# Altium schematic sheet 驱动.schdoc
size 594 x 419 mm; Symbol: Drawing-Symbol_A4; Company: 嘉立创EDA; Version: V1.0; Page Size: A4; @Project Name: FOC; @Update Date: 2026-07-20; @Create Date: 2026-07-20; Device: Drawing-Symbol_A4; @Board Name: Board1; @Page Name: P1; @Create Time: 00:30:19; @Page Count: 2; @Page No: 2; @Schematic Name: Schematic1; @Update Time: 00:30:19; @Assembly Variant: Basic; Border: 1; Title Block Position: 3; Size: A4; Width: 2338; Height: 1652; Region Start: 1; X Region Count: 6; Y Region Count: 4; Blade Width: 10
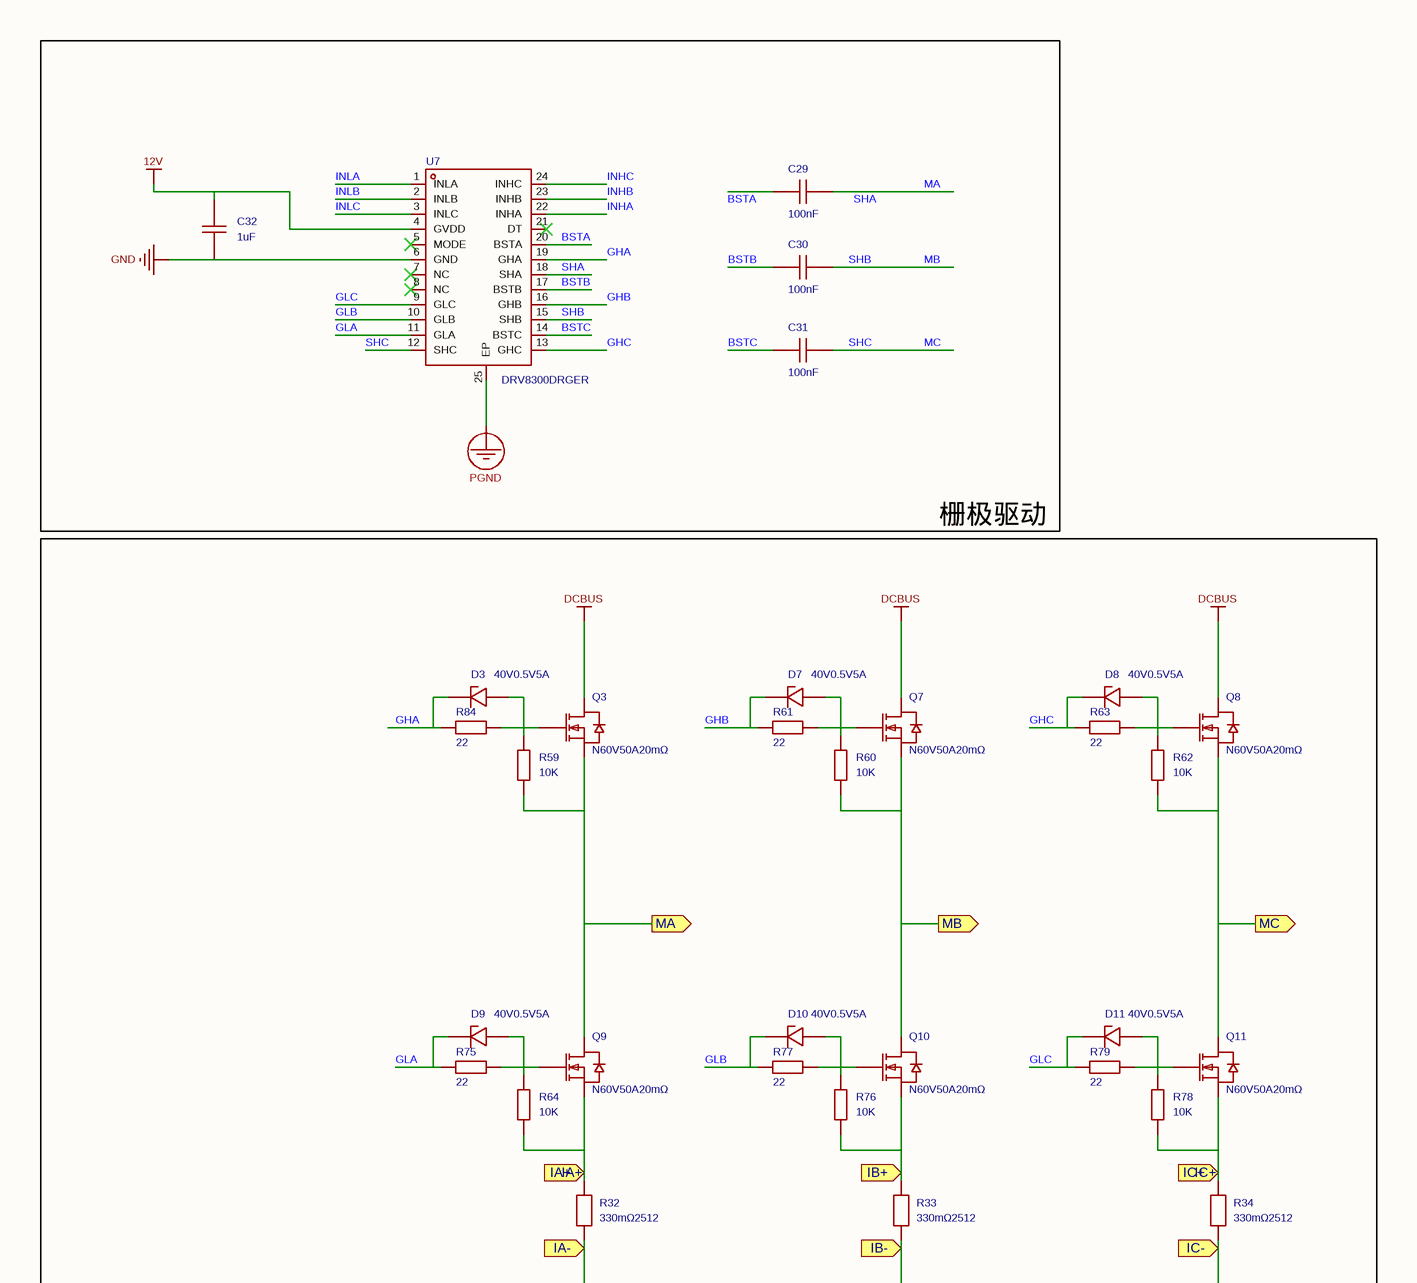
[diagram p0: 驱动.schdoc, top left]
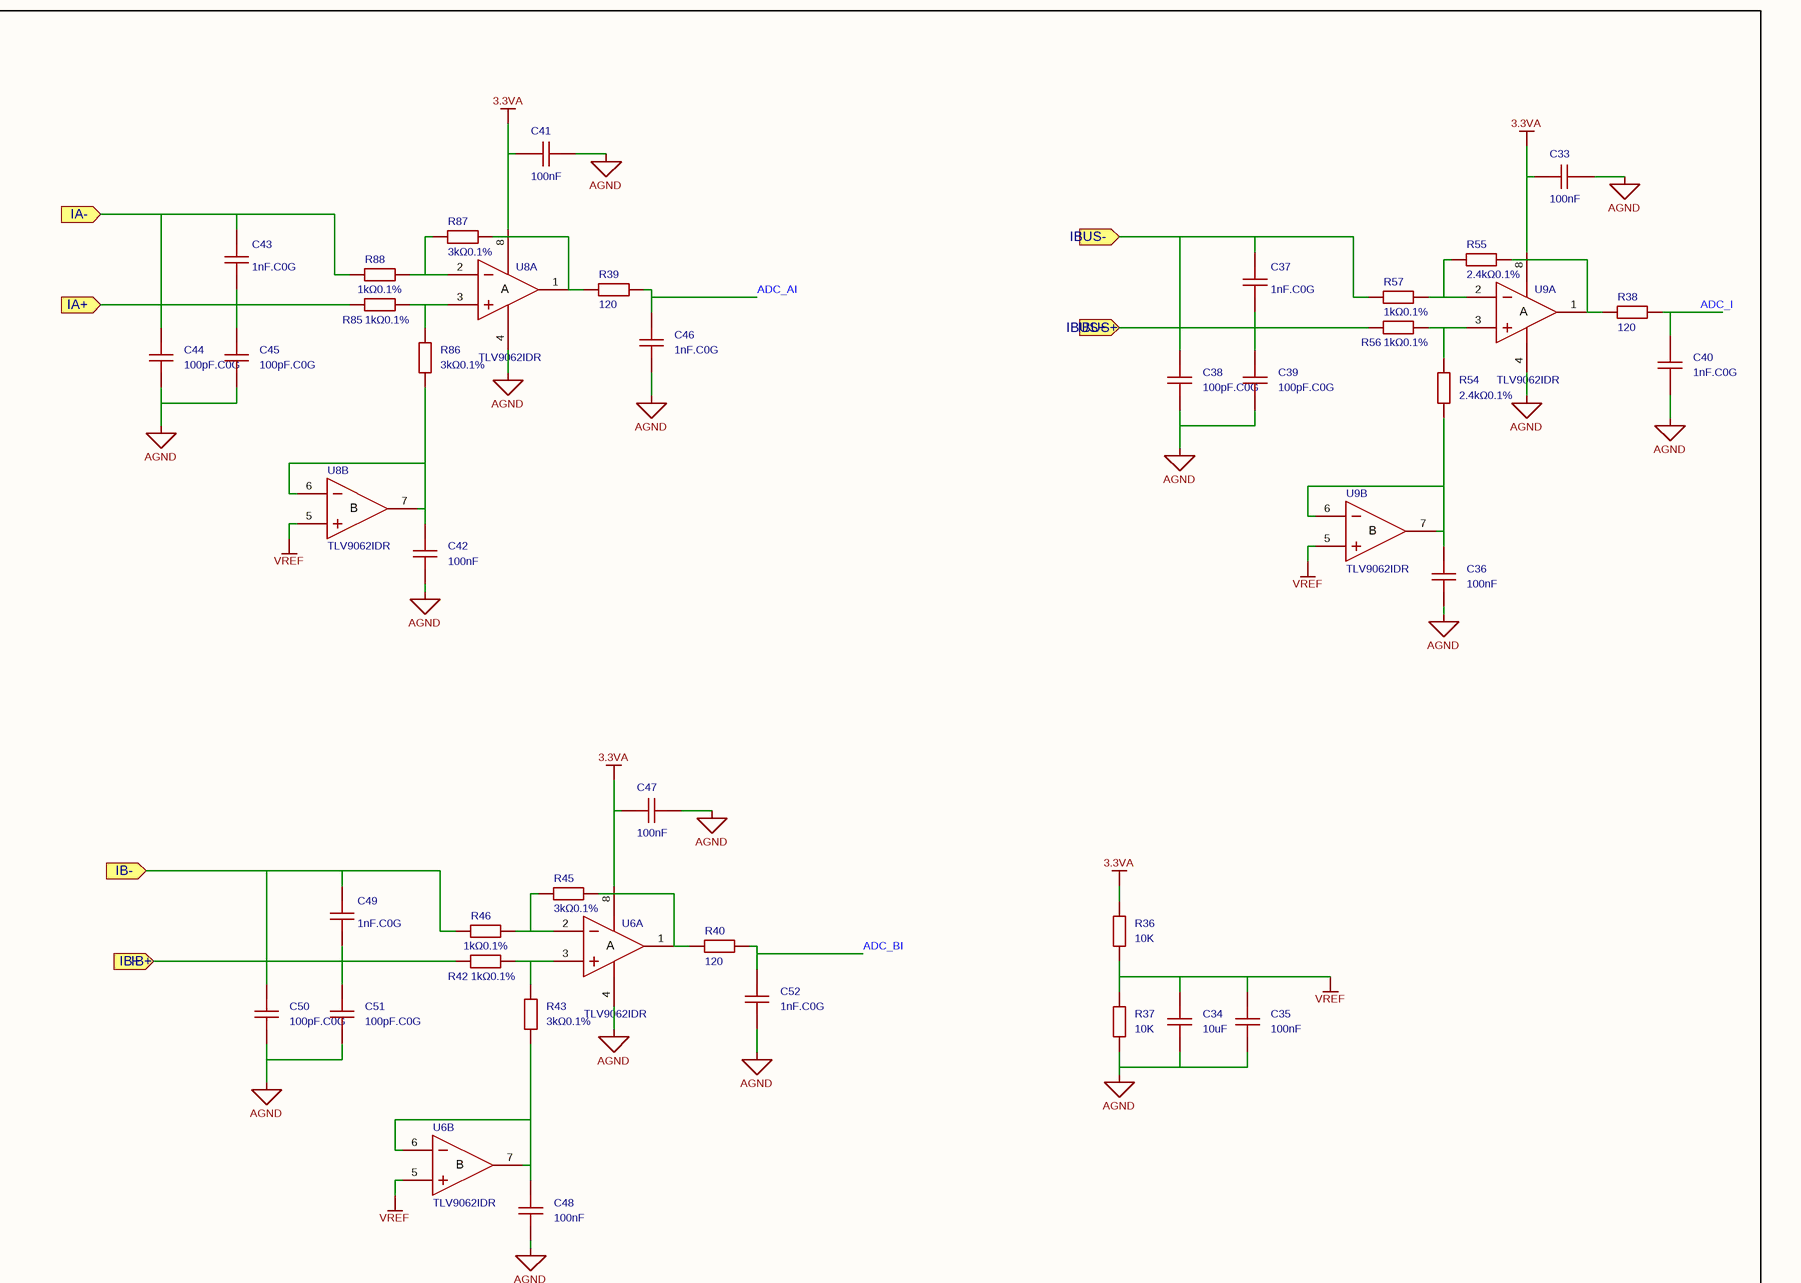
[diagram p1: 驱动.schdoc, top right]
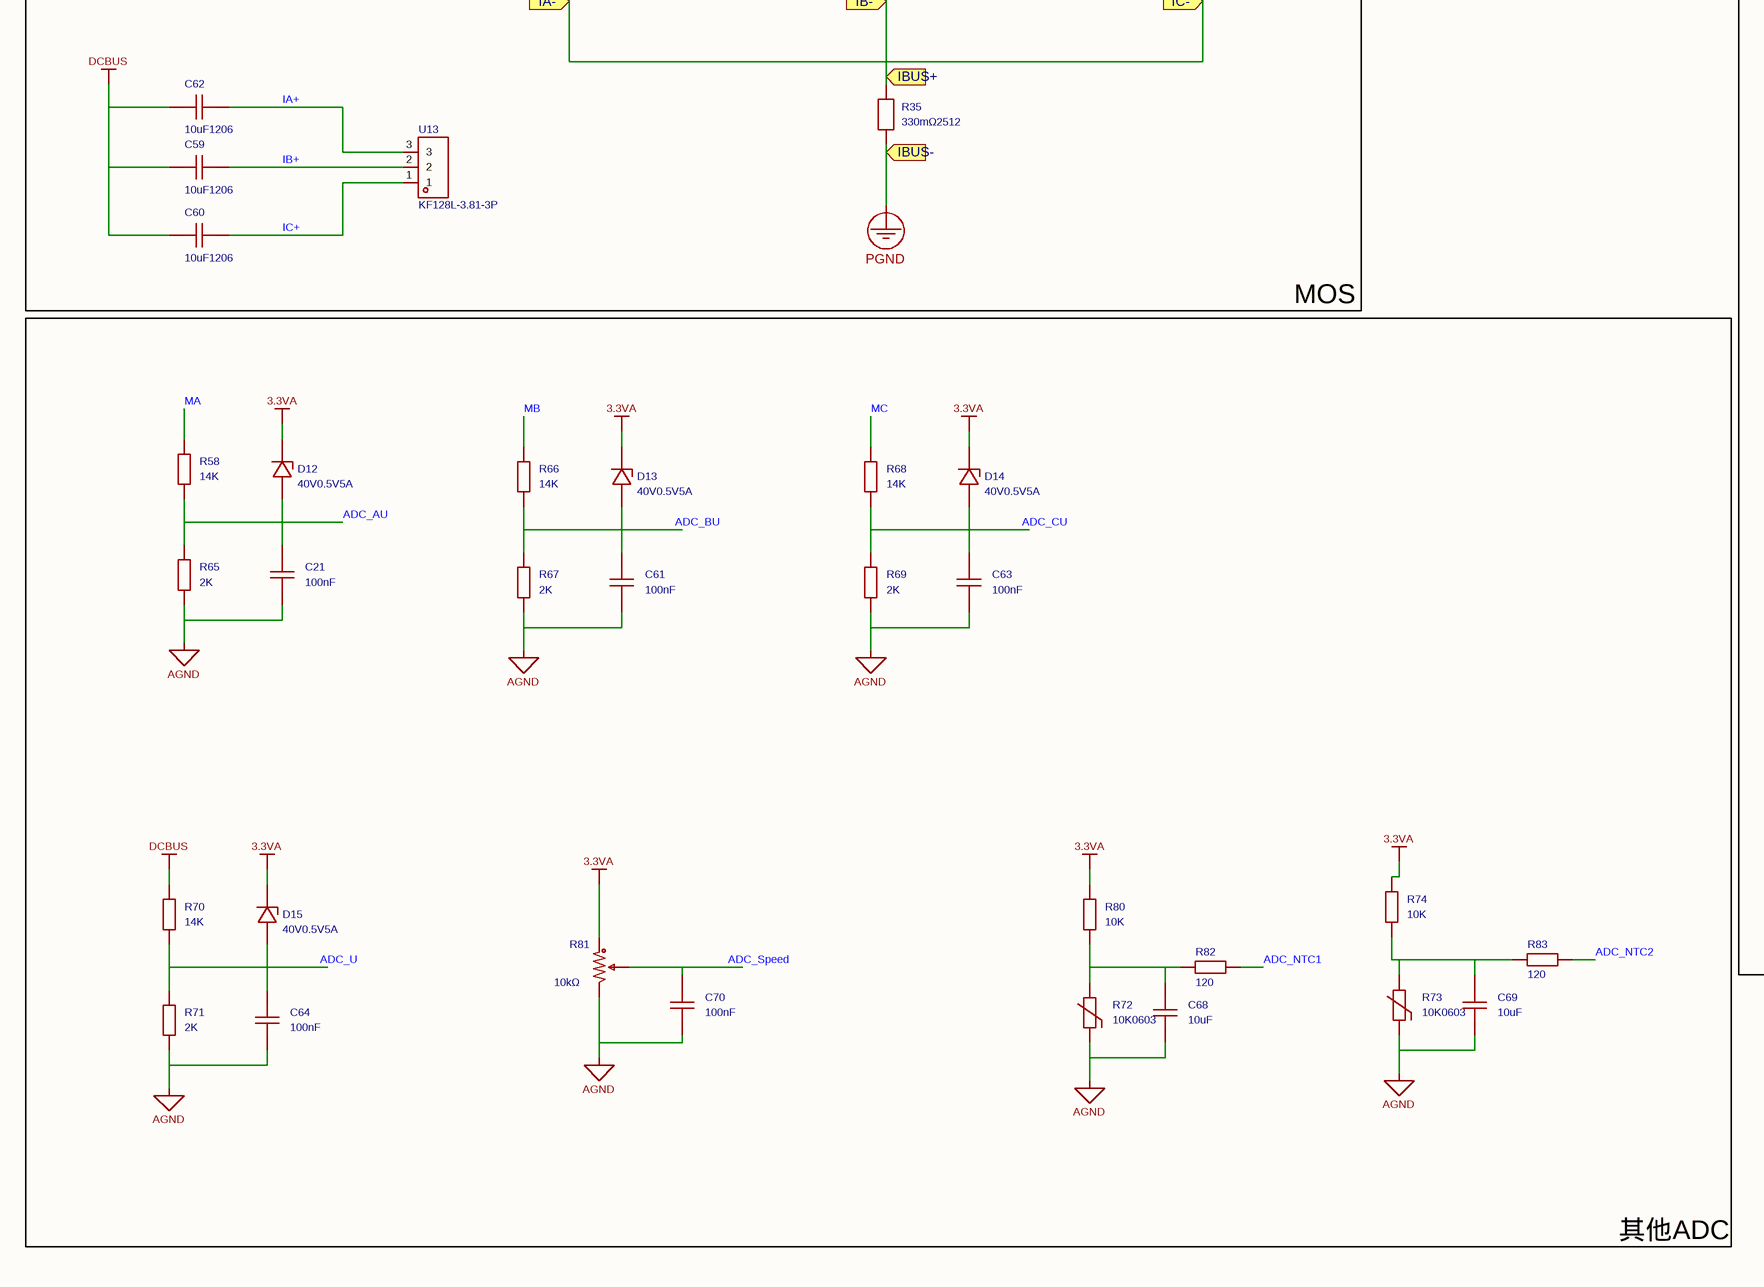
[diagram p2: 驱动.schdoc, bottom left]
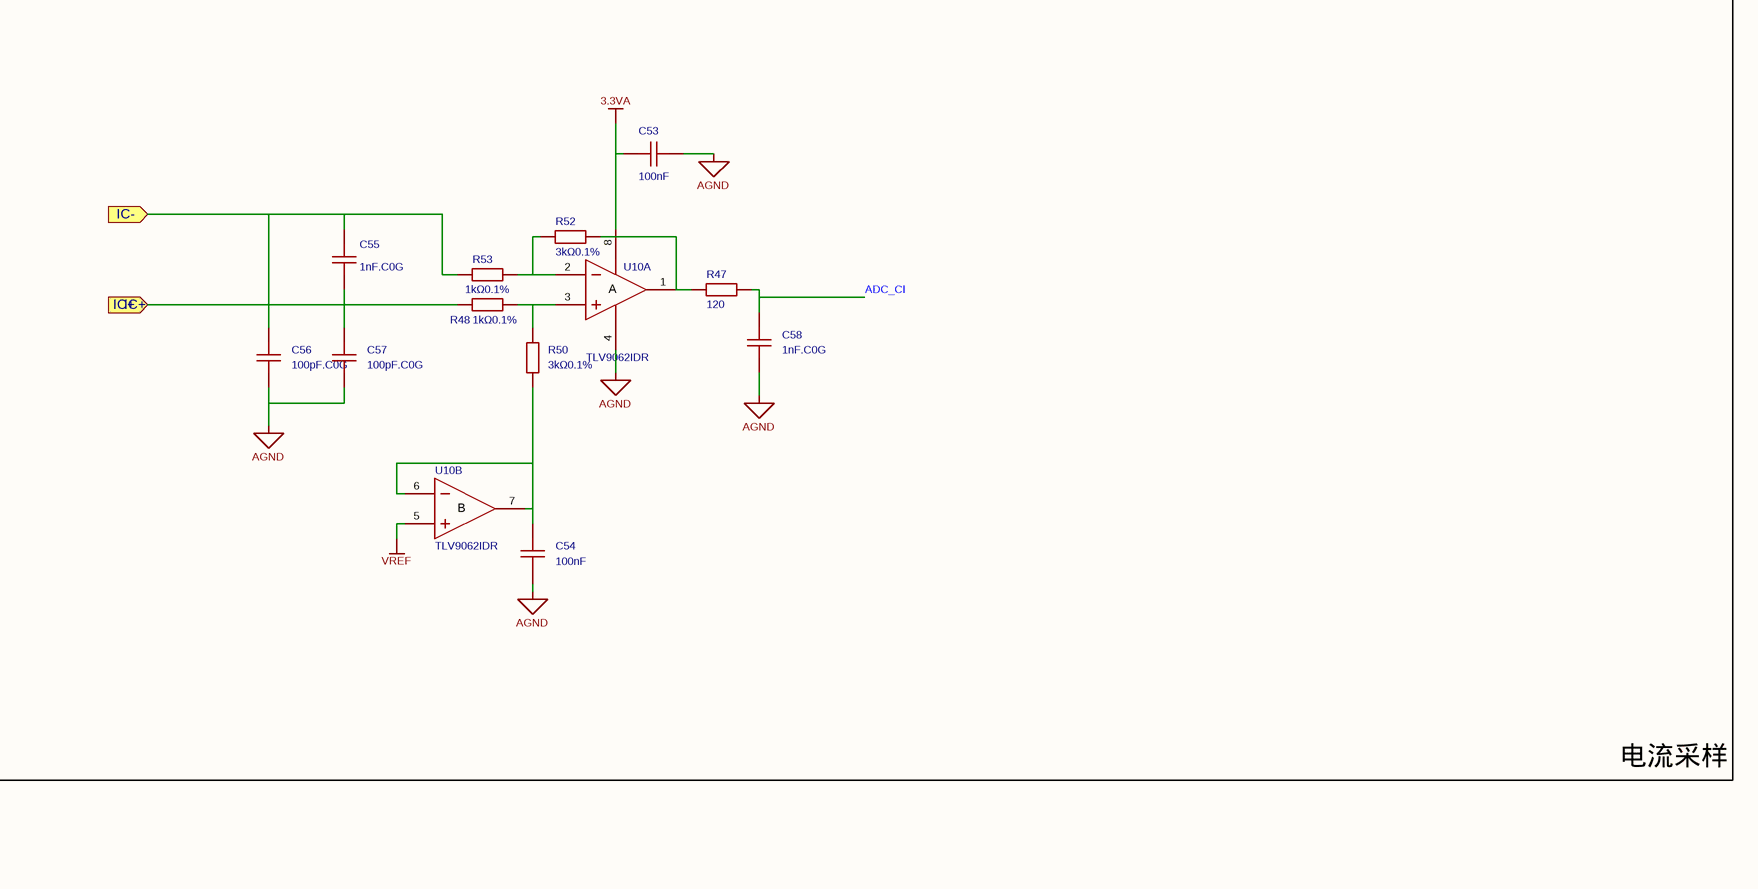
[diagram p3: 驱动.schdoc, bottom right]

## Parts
C21  100nF  [C0603]
C29  100nF  [C0603]
C30  100nF  [C0603]
C31  100nF  [C0603]
C32  1uF  [C0603]
C33  100nF  [C0603]
C34  10uF  [C0603]
C35  100nF  [C0603]
C36  100nF  [C0603]
C37  1nF.C0G  [C0603]
C38  100pF.C0G  [C0603]
C39  100pF.C0G  [C0603]
C40  1nF.C0G  [C0603]
C41  100nF  [C0603]
C42  100nF  [C0603]
C43  1nF.C0G  [C0603]
C44  100pF.C0G  [C0603]
C45  100pF.C0G  [C0603]
C46  1nF.C0G  [C0603]
C47  100nF  [C0603]
C48  100nF  [C0603]
C49  1nF.C0G  [C0603]
C50  100pF.C0G  [C0603]
C51  100pF.C0G  [C0603]
C52  1nF.C0G  [C0603]
C53  100nF  [C0603]
C54  100nF  [C0603]
C55  1nF.C0G  [C0603]
C56  100pF.C0G  [C0603]
C57  100pF.C0G  [C0603]
C58  1nF.C0G  [C0603]
C59  10uF1206  [C1206]
C60  10uF1206  [C1206]
C61  100nF  [C0603]
C62  10uF1206  [C1206]
C63  100nF  [C0603]
C64  100nF  [C0603]
C68  10uF  [C0603]
C69  10uF  [C0603]
C70  100nF  [C0603]
D3  40V0.5V5A  [SMA_L4.3-W2.6-LS5.0-FD]
D7  40V0.5V5A  [SMA_L4.3-W2.6-LS5.0-FD]
D8  40V0.5V5A  [SMA_L4.3-W2.6-LS5.0-FD]
D9  40V0.5V5A  [SMA_L4.3-W2.6-LS5.0-FD]
D10  40V0.5V5A  [SMA_L4.3-W2.6-LS5.0-FD]
D11  40V0.5V5A  [SMA_L4.3-W2.6-LS5.0-FD]
D12  40V0.5V5A  [SMA_L4.3-W2.6-LS5.0-FD]
D13  40V0.5V5A  [SMA_L4.3-W2.6-LS5.0-FD]
D14  40V0.5V5A  [SMA_L4.3-W2.6-LS5.0-FD]
D15  40V0.5V5A  [SMA_L4.3-W2.6-LS5.0-FD]
Q3  N60V50A20mΩ  [TO-252-2_L6.6-W6.1-P4.57-LS10.1-TL-CW]
Q7  N60V50A20mΩ  [TO-252-2_L6.6-W6.1-P4.57-LS10.1-TL-CW]
Q8  N60V50A20mΩ  [TO-252-2_L6.6-W6.1-P4.57-LS10.1-TL-CW]
Q9  N60V50A20mΩ  [TO-252-2_L6.6-W6.1-P4.57-LS10.1-TL-CW]
Q10  N60V50A20mΩ  [TO-252-2_L6.6-W6.1-P4.57-LS10.1-TL-CW]
Q11  N60V50A20mΩ  [TO-252-2_L6.6-W6.1-P4.57-LS10.1-TL-CW]
R32  330mΩ2512  [RES-SMD_L6.4-W3.2-JER2512XXXXXX]
R33  330mΩ2512  [RES-SMD_L6.4-W3.2-JER2512XXXXXX]
R34  330mΩ2512  [RES-SMD_L6.4-W3.2-JER2512XXXXXX]
R35  330mΩ2512  [RES-SMD_L6.4-W3.2-JER2512XXXXXX]
R36  10K  [R0603]
R37  10K  [R0603]
R38  120  [R0603]
R39  120  [R0603]
R40  120  [R0603]
R42  1kΩ0.1%  [R0603]
R43  3kΩ0.1%  [R0603]
R45  3kΩ0.1%  [R0603]
R46  1kΩ0.1%  [R0603]
R47  120  [R0603]
R48  1kΩ0.1%  [R0603]
R50  3kΩ0.1%  [R0603]
R52  3kΩ0.1%  [R0603]
R53  1kΩ0.1%  [R0603]
R54  2.4kΩ0.1%  [R0603]
R55  2.4kΩ0.1%  [R0603]
R56  1kΩ0.1%  [R0603]
R57  1kΩ0.1%  [R0603]
R58  14K  [R0603]
R59  10K  [R0603]
R60  10K  [R0603]
R61  22  [R0603]
R62  10K  [R0603]
R63  22  [R0603]
R64  10K  [R0603]
R65  2K  [R0603]
R66  14K  [R0603]
R67  2K  [R0603]
R68  14K  [R0603]
R69  2K  [R0603]
R70  14K  [R0603]
R71  2K  [R0603]
R72  10K0603  [R0603]
R73  10K0603  [R0603]
R74  10K  [R0603]
R75  22  [R0603]
R76  10K  [R0603]
R77  22  [R0603]
R78  10K  [R0603]
R79  22  [R0603]
R80  10K  [R0603]
R81  10kΩ  [RES-ADJ-TH_3362P]
R82  120  [R0603]
R83  120  [R0603]
R84  22  [R0603]
R85  1kΩ0.1%  [R0603]
R86  3kΩ0.1%  [R0603]
R87  3kΩ0.1%  [R0603]
R88  1kΩ0.1%  [R0603]
U6  TLV9062IDR  [SOIC-8_L5.0-W4.0-P1.27-LS6.0-BL]  (parts A,B of 2)
U7  DRV8300DRGER  [VQFN-24_L4.0-W4.0-P0.50-TL-EP2.5]
U8  TLV9062IDR  [SOIC-8_L5.0-W4.0-P1.27-LS6.0-BL]  (parts A,B of 2)
U9  TLV9062IDR  [SOIC-8_L5.0-W4.0-P1.27-LS6.0-BL]  (parts A,B of 2)
U10  TLV9062IDR  [SOIC-8_L5.0-W4.0-P1.27-LS6.0-BL]  (parts A,B of 2)
U13  KF128L-3.81-3P  [CONN-TH_3P-P3.81_KF128L-3.81-3P]

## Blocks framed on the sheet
栅极驱动: C29-C32 U7
电流采样: C33-C58 R36-R40 R42 R43 R45-R48 R50 R52-R57 R85-R88 U6 U8-U10
MOS: C59 C60 C62 D3 D7-D11 Q3 Q7-Q11 R32-R35 R59-R64 R75-R79 R84 U13
其他ADC: C21 C61 C63 C64 C68-C70 D12-D15 R58 R65-R74 R80-R83

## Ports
IA+ (in), IA- (in), IB+ (in), IB- (in), IBUS+ (in), IBUS- (in), IC+ (in), IC- (in), MA (out), MB (out), MC (out)

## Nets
3.3VA: C33.2 C41.2 C47.2 C53.2 D12.2(K) D13.2(K) D14.2(K) D15.2(K) R36.2 R74.2 R80.2 R81.1 U6.8(VCC) U8.8(VCC) U9.8(VCC) U10.8(VCC)
12V: C32.2 U7.4(GVDD)
AGND: C21.1 C33.1 C34.1 C35.1 C36.1 C38.1 C39.1 C40.1 C41.1 C42.1 C44.1 C45.1 C46.1 C47.1 C48.1 C50.1 C51.1 C52.1 C53.1 C54.1 C56.1 C57.1 C58.1 C61.1 C63.1 C64.1 C68.1 C69.1 C70.1 R37.1 R65.1 R67.1 R69.1 R71.1 R72.1 R73.1 R81.3 U6.4(VEE/GND) U8.4(VEE/GND) U9.4(VEE/GND) U10.4(VEE/GND)
DCBUS: C59.1 C60.1 C62.1 Q3.2(D) Q7.2(D) Q8.2(D) R70.2
GND: C32.1 U7.6(GND)
PGND: C37.2 C38.2 R35.1 R57.2 U7.25(EP) ; port IBUS-
VREF: C34.2 C35.2 R36.1 R37.2 U6.5(INB+) U8.5(INB+) U9.5(INB+) U10.5(INB+)
ADC_AI: C46.2 R39.1
ADC_AU: C21.2 D12.1(A) R58.1 R65.2
ADC_BI: C52.2 R40.1
ADC_BU: C61.2 D13.1(A) R66.1 R67.2
ADC_CI: C58.2 R47.1
ADC_CU: C63.2 D14.1(A) R68.1 R69.2
ADC_I: C40.2 R38.1
ADC_NTC1: R82.2
ADC_NTC2: R83.2
ADC_Speed: C70.2 R81.2
ADC_U: C64.2 D15.1(A) R70.1 R71.2
BSTA: C29.2 U7.20(BSTA)
BSTB: C30.1 U7.17(BSTB)
BSTC: C31.1 U7.14(BSTC)
GHA: D3.2(K) R84.1 U7.19(GHA)
GHB: D7.2(K) R61.1 U7.16(GHB)
GHC: D8.2(K) R63.1 U7.13(GHC)
GLA: D9.2(K) R75.1 U7.11(GLA)
GLB: D10.2(K) R77.1 U7.10(GLB)
GLC: D11.2(K) R79.1 U7.9(GLC)
IA+: C43.1 C45.2 C62.2 Q9.3(S) R32.2 R64.1 R85.2 U13.3 ; port IA+
IB+: C49.1 C51.2 C59.2 Q10.3(S) R33.2 R42.2 R76.1 U13.2 ; port IB+
IBUS+: C37.1 C39.2 C43.2 C44.2 C49.2 C50.2 C55.2 C56.2 R32.1 R33.1 R34.1 R35.2 R46.2 R53.2 R56.2 R88.2 ; port IA-, port IB-, port IC-, port IBUS+
IC+: C55.1 C57.2 C60.2 Q11.3(S) R34.2 R48.2 R78.1 U13.1 ; port IC+
INHA: U7.22(INHA)
INHB: U7.23(INHB)
INHC: U7.24(INHC)
INLA: U7.1(INLA)
INLB: U7.2(INLB)
INLC: U7.3(INLC)
MA: Q3.3(S) Q9.2(D) R59.1 ; port MA
MA: C29.1 R58.2 U7.18(SHA)  [also labelled SHA]  [a separate net that carries the same name]
MB: C30.2 R66.2 U7.15(SHB)  [also labelled SHB]
MB: Q7.3(S) Q10.2(D) R60.1 ; port MB  [a separate net that carries the same name]
MC: C31.2 R68.2 U7.12(SHC)  [also labelled SHC]
MC: Q8.3(S) Q11.2(D) R62.1 ; port MC  [a separate net that carries the same name]
NetC36_2: C36.2 R54.2 U9.6(INB-) U9.7(OUTB)
NetC42_2: C42.2 R86.1 U8.6(INB-) U8.7(OUTB)
NetC48_2: C48.2 R43.1 U6.6(INB-) U6.7(OUTB)
NetC54_2: C54.2 R50.1 U10.6(INB-) U10.7(OUTB)
NetC68_2: C68.2 R72.2 R80.1 R82.1
NetC69_2: C69.2 R73.2 R74.1 R83.1
NetD3_1: D3.1(A) Q3.1(G) R59.2 R84.2
NetD7_1: D7.1(A) Q7.1(G) R60.2 R61.2
NetD8_1: D8.1(A) Q8.1(G) R62.2 R63.2
NetD9_1: D9.1(A) Q9.1(G) R64.2 R75.2
NetD10_1: D10.1(A) Q10.1(G) R76.2 R77.2
NetD11_1: D11.1(A) Q11.1(G) R78.2 R79.2
NetR38_2: R38.2 R55.1 U9.1(OUTA)
NetR39_2: R39.2 R87.1 U8.1(OUTA)
NetR40_2: R40.2 R45.1 U6.1(OUTA)
NetR42_1: R42.1 R43.2 U6.3(INA+)
NetR45_2: R45.2 R46.1 U6.2(INA-)
NetR47_2: R47.2 R52.1 U10.1(OUTA)
NetR48_1: R48.1 R50.2 U10.3(INA+)
NetR52_2: R52.2 R53.1 U10.2(INA-)
NetR54_1: R54.1 R56.1 U9.3(INA+)
NetR55_2: R55.2 R57.1 U9.2(INA-)
NetR85_1: R85.1 R86.2 U8.3(INA+)
NetR87_2: R87.2 R88.1 U8.2(INA-)

Not connected (* = marked no-connect by the designer): U7 5(MODE)* 7(NC)* 8(NC)* 21(DT)*

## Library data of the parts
C21 C29-C58 C61 C63 C64 C68-C70 = CAP_0603: Symbol: Capacitance; 3D Model: ac125912035d415993ca9572d50418b10819f05c4eef4c71ace90d822a990e87; 3D Model Transform: 62.992,31.496,0,0,0,0,0,0,0; ConvertToPcb: yes; ModelName: C0603_L1.6-W0.8-H0.8
C59 C60 C62 = CAP_1206: Symbol: Capacitance; 3D Model: e4be705b945545a48e666415e3682bd80819f05c4eef4c71ace90d822a990e87; 3D Model Transform: 125.984,62.992,0,0,0,0,0,0,0; ConvertToPcb: yes; ModelName: C1206_L3.2-W1.6-H1.3
D3 = SS54_C7420369: 二极管配置:独立式;正向压降(Vf):550mV@5A;直流反向耐压(Vr):40V;整流电流:5A;; Manufacturer: R+O(宏嘉诚); AddInBom: yes; ModelId: 7e24bebe6cd74171ae8c9de6fc5b78aa0819f05c4eef4c71ace90d822a990e87; ModelTransform: 198.4248,103.5431,0,180,0,0,-0.001,0,0; Diode Configuration: 独立式; Voltage - DC Reverse(Vr): 40V; Current - Rectified: 5A; Reverse Leakage Current (Ir): 50uA@40V; Operating Junction Temperature Range: -55℃~+125℃; Non-Repetitive Peak Forward Surge Current: 120A
D7-D15 = SS54_C7420369: 二极管配置:独立式;正向压降(Vf):550mV@5A;直流反向耐压(Vr):40V;整流电流:5A;; Manufacturer: R+O(宏嘉诚); 3D Model: 7e24bebe6cd74171ae8c9de6fc5b78aa0819f05c4eef4c71ace90d822a990e87; 3D Model Transform: 198.4248,103.5431,0,180,0,0,-0.001,0,0; Diode Configuration: 独立式; Voltage - DC Reverse(Vr): 40V; Current - Rectified: 5A; Reverse Leakage Current (Ir): 50uA@40V; Operating Junction Temperature Range: -55℃~+125℃; Non-Repetitive Peak Forward Surge Current: 120A; AddInBom: yes
Q3 Q7-Q11 = NCE6050KA: 数量:1个N沟道;漏源电压(Vdss):60V;连续漏极电流(Id):50A;导通电阻(RDS(on)):20mΩ@10V,20A;耗散功率(Pd):85W;阈值电压(Vgs(th)):2.5V;; Manufacturer: NCE(无锡新洁能); 3D Model: 5d8ef1b124a64febb2ca91a0282fbfcc0819f05c4eef4c71ace90d822a990e87; 3D Model Transform: 397.637,259.842,0,0,0,0,38.819,0,0; Number: 1个N沟道; Drain to Source Voltage: 60V; Current - Continuous Drain(Id): 50A; Pd - Power Dissipation: 85W; Gate Threshold Voltage (Vgs(th)): 2.5V; Gate Charge(Qg): 50nC@30V; Input Capacitance(Ciss): 2.05nF@30V; Reverse Transfer Capacitance (Crss@Vds): 120pF; AddInBom: yes
R32-R35 = JER2512F3R330: 电阻类型:采样电阻;阻值:330mΩ;精度:±1%;功率:3W;温度系数:±50ppm/℃;; Manufacturer: JIERR(捷而瑞); AddInBom: yes; ModelId: 86940c9ee0e84485a3b46b31e13b14ff0819f05c4eef4c71ace90d822a990e87; ModelTransform: 252.7554,126.7714,0,0,0,0,0,0,0; Tolerance: ±1%; Power(Watts): 3W
R36-R40 R42 R43 R45-R48 R50 R52-R71 R74-R80 R82-R88 = Res_0603: Symbol: 电阻; 3D Model: fc143cca1e79419f9cd78b61e9279f080819f05c4eef4c71ace90d822a990e87; 3D Model Transform: 31.8897,63.7794,0,90,0,0,0,0,0; ConvertToPcb: yes
R72 R73 = HNTC0603-103F3450FA: 功率:100mW;阻值:10kΩ;电阻精度:±1%;B值精度:±1%;B值(25℃/50℃):-;最大稳态电流(25℃):310uA;; Manufacturer: R+O(宏嘉诚); AddInBom: yes; ModelId: fc143cca1e79419f9cd78b61e9279f080819f05c4eef4c71ace90d822a990e87; ModelTransform: 31.8897,63.7794,0,90,0,0,0,0,0; Power(Watts): 100mW; Resistance @ 25℃: 10kΩ; Resistance Tolerance: ±1%; B Constant (25℃/85℃): 3450K; Steady State Current (Max): 310uA; Dissipation Factor: 1mW/℃; Thermal Time Constant: 5s; Pitch: 0.3mm
R81 = 3362P-1-103_C48997914: 阻值:10kΩ;精度:±10%;功率:500mW;温度系数:±250ppm/℃;; Manufacturer: JIERR(捷而瑞); AddInBom: yes; ModelId: b1c5cb968ae748a39271ba681de641230819f05c4eef4c71ace90d822a990e87; ModelName: 3362P; ModelTransform: 271.653,279.527,0,0,0,0,0,-49.803,-232.283; Tolerance: ±10%; Power(Watts): 500mW; Number of Turns: 1
U6 U10 = TLV9062IDR: 放大器数:2;轨到轨:轨到轨输入,轨到轨输出;增益带宽积(GBW):10MHz;输入失调电压(Vos):1.6mV;压摆率(SR):6.5V/us;输入偏置电流(Ib):0.5pA;; Manufacturer: TI(德州仪器); Relevance: []; 3D Model: 7abc64c95a1a4a04a4ef38f9097c870b0819f05c4eef4c71ace90d822a990e87; 3D Model Transform: 192.913,236.22,0,0,0,0,0,0,0; Number of Channels: 2; Maximum Power Supply Range (Vdd-Vss): 5.5V; Gain Bandwidth Product: 10MHz; Vos - Input Offset Voltage: 1.6mV; Input Offset Voltage Drift(Vos TC): 530nV/℃; Ib - Input Bias Current: 0.5pA; Input Offset Current(Ios): 0.05pA; Input Voltage Noise Density: 10nV/√Hz@1kHz; Common Mode Rejection Ratio(CMRR): 103dB; Quiescent Current: 538uA; Output Current: 50mA; Single supply: 1.8V~5.5V; AddInBom: yes
U7 = DRV8300DRGER_C3655801: DRV8300 具有自举二极管的最大 100V 简单三相栅极驱动器; Manufacturer: TI(德州仪器); AddInBom: yes; ModelId: 45d01521fd6b4217a75fbd67391c0e910819f05c4eef4c71ace90d822a990e87; ModelTransform: 158.267,158.267,0,0,0,0,0,0,0
U8 U9 = TLV9062IDR: 放大器数:2;轨到轨:轨到轨输入,轨到轨输出;增益带宽积(GBW):10MHz;输入失调电压(Vos):1.6mV;压摆率(SR):6.5V/us;输入偏置电流(Ib):0.5pA;; Manufacturer: TI(德州仪器); Relevance: []; AddInBom: yes; ModelId: 7abc64c95a1a4a04a4ef38f9097c870b0819f05c4eef4c71ace90d822a990e87; ModelTransform: 192.913,236.22,0,0,0,0,0,0,0; Number of Channels: 2; Maximum Power Supply Range (Vdd-Vss): 5.5V; Gain Bandwidth Product: 10MHz; Vos - Input Offset Voltage: 1.6mV; Input Offset Voltage Drift(Vos TC): 530nV/℃; Ib - Input Bias Current: 0.5pA; Input Offset Current(Ios): 0.05pA; Input Voltage Noise Density: 10nV/√Hz@1kHz; Common Mode Rejection Ratio(CMRR): 103dB; Quiescent Current: 538uA; Output Current: 50mA; Single supply: 1.8V~5.5V
U13 = KF128L-3.81-3P: 结构:1x3P;间距:3.81mm;颜色:绿色;安装方式:直插;排数:1;每排PIN数:3;额定电流:10A;额定电压:300V;线规 - AWG:16~26;线规 - 平方毫米:1;工作温度:-40℃~+105℃;; Manufacturer: KEFA(科发); AddInBom: yes; ModelId: f99726cc69d44390a4a603ea64f3bfe00819f05c4eef4c71ace90d822a990e87; ModelTransform: 469.72347,295.275,0,0,0,0,-9.842,-5.905,-137.795; Number of Positions or Pins: 1x3P; Pitch: 3.81mm; Number of PINs Per Row: 3; Current Rating: 10A; Voltage Rating (Max): 300V; Wire Gauge - AWG: 16~26; Wire Gauge - mm2: 1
